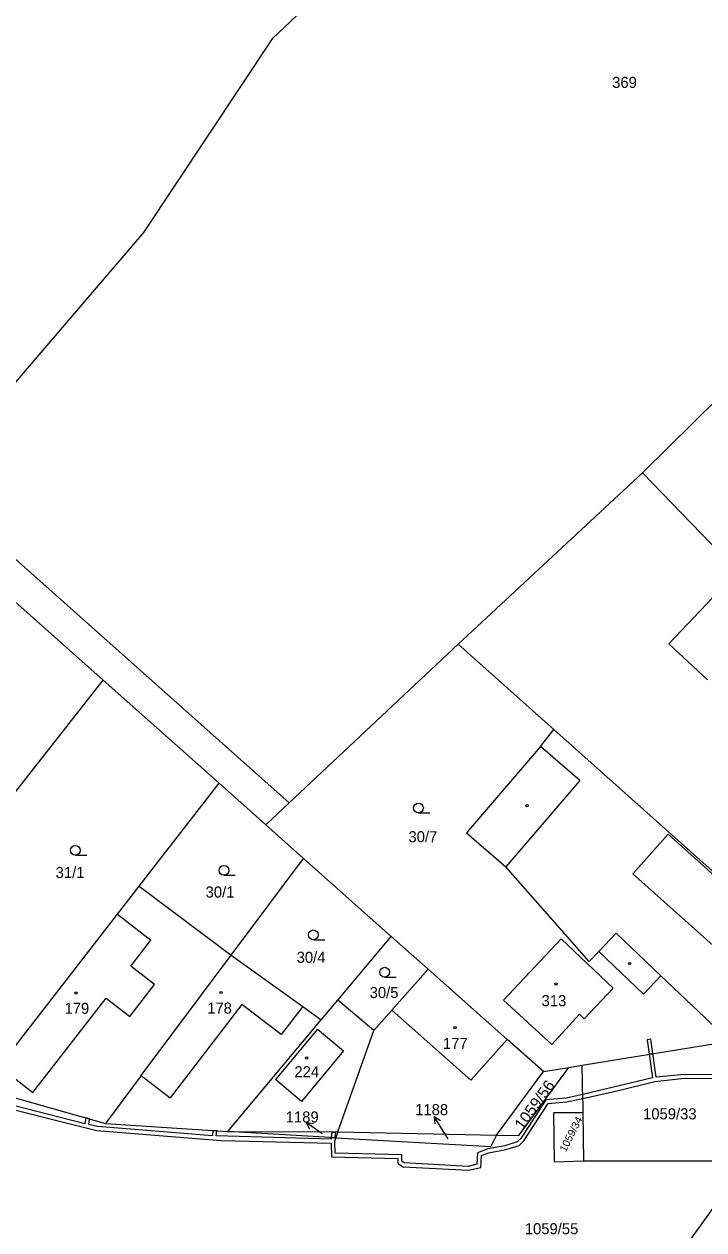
# Model space of a CAD drawing. Extents: x -694609 to -690140, y -1033292 to -1029794.
# Drawn here: x -692407.6 to -692303.2, y -1031470.7 to -1031285.6 of the extents above; entities that cross this region are included whole.
import ezdxf
from ezdxf.enums import TextEntityAlignment as Align

# ---------------------------------------------------------------- set-up
doc = ezdxf.new("R2010")
doc.units = 0
doc.header["$LTSCALE"] = 0.68
for name, color, linetype, lineweight in [('1', 7, 'Continuous', 25), ('13', 7, 'Continuous', 13), ('3', 7, 'Continuous', 25), ('4', 7, 'Continuous', 13), ('5', 7, 'Continuous', 25), ('7', 7, 'Continuous', 13)]:
    doc.layers.add(name, color=color, linetype=linetype, lineweight=lineweight)
doc.layers.add('2', color=7, linetype='Continuous')

msp = doc.modelspace()

# ---------------------------------------------------------------- linework, layer by layer
at = {"layer": '1'}
for p, q in [((-692351.12, -1031270.27), (-692369.47, -1031287.83)), ((-692369.47, -1031287.83), (-692389.22, -1031317.57)), ((-692389.22, -1031317.57), (-692422.13, -1031355.95)), ((-692300.88, -1031342.86), (-692312.61, -1031354.44)), ((-692340.93, -1031380.74), (-692312.61, -1031354.44)), ((-692297.6, -1031369.99), (-692312.61, -1031354.44)), ((-692366.85, -1031405.11), (-692422.13, -1031355.95)), ((-692395.42, -1031386.28), (-692410.37, -1031372.97)), ((-692308.57, -1031380.71), (-692299.9, -1031371.58)), ((-692366.85, -1031405.11), (-692340.93, -1031380.74)), ((-692340.93, -1031380.74), (-692326.24, -1031393.88)), ((-692302.61, -1031386.24), (-692308.57, -1031380.71)), ((-692420.58, -1031418.3), (-692395.42, -1031386.28)), ((-692377.64, -1031402.11), (-692395.42, -1031386.28)), ((-692328.3, -1031396.47), (-692326.24, -1031393.88)), ((-692282.48, -1031432.88), (-692326.24, -1031393.88)), ((-692328.3, -1031396.47), (-692339.66, -1031409.74)), ((-692389.89, -1031417.89), (-692377.64, -1031402.11)), ((-692370.46, -1031408.5), (-692377.64, -1031402.11)), ((-692370.46, -1031408.5), (-692366.85, -1031405.11)), ((-692364.66, -1031413.68), (-692370.46, -1031408.5)), ((-692339.66, -1031409.74), (-692333.58, -1031414.94)), ((-692375.76, -1031428.52), (-692364.66, -1031413.68)), ((-692351.21, -1031425.61), (-692364.66, -1031413.68)), ((-692320.78, -1031429.49), (-692333.58, -1031414.94)), ((-692393.22, -1031422.18), (-692389.89, -1031417.89)), ((-692389.89, -1031417.89), (-692375.76, -1031428.52)), ((-692411.4, -1031445.59), (-692393.22, -1031422.18)), ((-692345.54, -1031430.65), (-692351.21, -1031425.61)), ((-692325.13, -1031425.99), (-692333.94, -1031435.42)), ((-692317.12, -1031433.56), (-692325.13, -1031425.99)), ((-692389.58, -1031446.98), (-692375.76, -1031428.52)), ((-692375.76, -1031428.52), (-692364.79, -1031436.37)), ((-692319.32, -1031427.95), (-692320.78, -1031429.49)), ((-692312.45, -1031434.47), (-692319.32, -1031427.95)), ((-692345.54, -1031430.65), (-692351.11, -1031436.93)), ((-692333.38, -1031441.43), (-692345.54, -1031430.65)), ((-692309.78, -1031431.66), (-692312.45, -1031434.47)), ((-692299.22, -1031441.68), (-692309.78, -1031431.66)), ((-692317.12, -1031433.56), (-692321.56, -1031438.27)), ((-692353.88, -1031440.05), (-692359.42, -1031435.41)), ((-692326.55, -1031442.22), (-692333.94, -1031435.42)), ((-692364.79, -1031436.37), (-692361.94, -1031438.41)), ((-692351.11, -1031436.93), (-692353.88, -1031440.05)), ((-692322.3, -1031437.56), (-692326.55, -1031442.22)), ((-692321.56, -1031438.27), (-692322.3, -1031437.56)), ((-692376.31, -1031455.57), (-692361.94, -1031438.41)), ((-692359.39, -1031455.63), (-692353.88, -1031440.05)), ((-692327.81, -1031446.38), (-692333.38, -1031441.43)), ((-692321.9, -1031445.37), (-692299.22, -1031441.68)), ((-692323.94, -1031445.72), (-692321.9, -1031445.37)), ((-692321.78, -1031450.93), (-692321.9, -1031445.37)), ((-692389.58, -1031446.98), (-692395.05, -1031454.33)), ((-692335.02, -1031456.14), (-692327.81, -1031446.38)), ((-692331.58, -1031456.21), (-692323.94, -1031445.72)), ((-692327.81, -1031446.38), (-692323.94, -1031445.72)), ((-692414.04, -1031448.99), (-692395.05, -1031454.33)), ((-692326.22, -1031452.64), (-692321.76, -1031452.64)), ((-692326.13, -1031460.27), (-692326.22, -1031452.64)), ((-692321.78, -1031450.93), (-692321.76, -1031452.64)), ((-692321.76, -1031452.64), (-692321.65, -1031460.14)), ((-692395.05, -1031454.33), (-692376.31, -1031455.57)), ((-692359.7, -1031456.52), (-692376.31, -1031455.57)), ((-692376.31, -1031455.57), (-692359.39, -1031455.63)), ((-692359.39, -1031455.63), (-692359.7, -1031456.52)), ((-692359.39, -1031455.63), (-692335.02, -1031456.14)), ((-692335.02, -1031456.14), (-692335.92, -1031457.88)), ((-692335.02, -1031456.14), (-692331.58, -1031456.21)), ((-692359.7, -1031456.52), (-692335.92, -1031457.88)), ((-692321.65, -1031460.14), (-692326.13, -1031460.27)), ((-692296.63, -1031460.11), (-692321.65, -1031460.14)), ((-692296.63, -1031460.11), (-692310.42, -1031479.32))]:
    msp.add_line(p, q, dxfattribs=at)
msp.add_lwpolyline([(-692361.94, -1031438.41), (-692359.42, -1031435.41), (-692351.21, -1031425.61)], dxfattribs=at)
at = {"layer": '13'}
for points in [[(-692311.92, -1031441.51), (-692311.61, -1031443.7), (-692311.02, -1031443.6), (-692311.33, -1031441.39)], [(-692360.33, -1031455.72), (-692360.4, -1031456.48), (-692359.8, -1031456.51), (-692359.73, -1031455.73)]]:
    msp.add_lwpolyline(points, close=True, dxfattribs=at)
for points in [[(-692292.95, -1031446.89), (-692306.17, -1031446.8), (-692310.5, -1031447.24), (-692311.02, -1031443.6), (-692311.61, -1031443.7), (-692311.09, -1031447.35), (-692321.8, -1031449.88), (-692324.35, -1031450.44), (-692327.46, -1031450.69), (-692331.3, -1031456.62), (-692331.88, -1031457.18), (-692333.73, -1031457.77), (-692336.39, -1031458.25), (-692337.93, -1031458.83), (-692338.03, -1031460.6), (-692339.41, -1031460.92), (-692349.19, -1031460.39), (-692349.59, -1031460.14), (-692349.56, -1031459.13), (-692359.81, -1031458.88), (-692359.85, -1031457.08), (-692359.7, -1031456.52), (-692360.4, -1031456.48), (-692360.42, -1031456.76), (-692378.06, -1031456.26), (-692377.99, -1031455.46), (-692378.59, -1031455.42)], [(-692414.65, -1031450.86), (-692396.4, -1031455.42), (-692377.33, -1031456.93), (-692360.44, -1031457.36), (-692360.39, -1031459.46), (-692350.18, -1031459.71), (-692350.21, -1031460.46), (-692349.37, -1031460.99), (-692339.35, -1031461.52), (-692337.45, -1031461.08), (-692337.35, -1031459.25), (-692336.23, -1031458.83), (-692333.59, -1031458.35), (-692331.56, -1031457.7), (-692330.84, -1031457), (-692327.12, -1031451.27), (-692324.27, -1031451.04), (-692321.79, -1031450.49), (-692316.31, -1031449.28), (-692310.71, -1031447.87), (-692306.15, -1031447.4), (-692292.65, -1031447.49)], [(-692378.59, -1031455.42), (-692378.66, -1031456.24), (-692396.3, -1031454.82), (-692397.64, -1031454.51), (-692397.52, -1031453.63), (-692398.11, -1031453.47), (-692398.23, -1031454.37), (-692413.03, -1031450.59)]]:
    msp.add_lwpolyline(points, dxfattribs=at)
at = {"layer": '3'}
for p, q in [((-692347.013, -1031406.65), (-692345.263, -1031406.65)), ((-692399.693, -1031413.16), (-692397.943, -1031413.16)), ((-692376.893, -1031416.23), (-692375.143, -1031416.23)), ((-692363.153, -1031426.13), (-692361.403, -1031426.13)), ((-692352.213, -1031431.86), (-692350.463, -1031431.86))]:
    msp.add_line(p, q, dxfattribs=at)
for centre in [(-692347.0129, -1031405.8998), (-692399.6929, -1031412.4098), (-692376.8929, -1031415.4798), (-692363.1529, -1031425.3798), (-692352.2129, -1031431.1098)]:
    msp.add_circle(centre, 0.75, dxfattribs=at)
at = {"layer": '4'}
for p, q in [((-692322.22, -1031401.67), (-692328.3, -1031396.47)), ((-692322.22, -1031401.67), (-692333.58, -1031414.94)), ((-692308.68, -1031409.94), (-692314.1, -1031416)), ((-692286.89, -1031429.49), (-692308.68, -1031409.94)), ((-692301.77, -1031427.03), (-692314.1, -1031416)), ((-692393.22, -1031422.18), (-692388.09, -1031426.19)), ((-692391.2, -1031430.2), (-692388.09, -1031426.19)), ((-692316.65, -1031425.13), (-692319.32, -1031427.95)), ((-692309.78, -1031431.66), (-692316.65, -1031425.13)), ((-692387.57, -1031433.02), (-692391.2, -1031430.2)), ((-692391.36, -1031437.9), (-692387.57, -1031433.02)), ((-692406.25, -1031449.58), (-692394.99, -1031435.08)), ((-692394.99, -1031435.08), (-692391.36, -1031437.9)), ((-692364.79, -1031436.37), (-692368.11, -1031440.69)), ((-692362.5, -1031439.86), (-692368.99, -1031447.61)), ((-692362.5, -1031439.86), (-692358.51, -1031443.2)), ((-692411.4, -1031445.59), (-692406.25, -1031449.58)), ((-692389.58, -1031446.98), (-692385.13, -1031450.4))]:
    msp.add_line(p, q, dxfattribs=at)
for points in [[(-692368.11, -1031440.69), (-692374.12, -1031436.07), (-692385.13, -1031450.4)], [(-692351.11, -1031436.93), (-692338.96, -1031447.71), (-692333.38, -1031441.43)], [(-692358.51, -1031443.2), (-692365, -1031450.95), (-692368.99, -1031447.61)]]:
    msp.add_lwpolyline(points, dxfattribs=at)
at = {"layer": '5'}
for centre in [(-692330.3468, -1031405.5492), (-692314.5968, -1031429.7792), (-692399.5968, -1031434.3092), (-692377.3268, -1031434.2292), (-692325.8868, -1031432.9092), (-692341.4268, -1031439.6492), (-692364.1768, -1031444.2892)]:
    msp.add_circle(centre, 0.175, dxfattribs=at)
at = {"layer": '7'}
for p, q in [((-692364.248, -1031454.176), (-692363.732, -1031455.17)), ((-692344.6, -1031453.285), (-692344.494, -1031454.4))]:
    msp.add_line(p, q, dxfattribs=at)
for points in [[(-692361.82, -1031455.94), (-692364.248, -1031454.176), (-692363.143, -1031454.36)], [(-692342.45, -1031456.72), (-692343.01, -1031455.83), (-692344.6, -1031453.285), (-692343.645, -1031453.869)]]:
    msp.add_lwpolyline(points, dxfattribs=at)

# ---------------------------------------------------------------- texts
at = {"layer": '2'}
for s, p in [('369', (-692315.379, -1031295.355)), ('30/7', (-692346.339, -1031411.165)), ('31/1', (-692400.519, -1031416.655)), ('30/1', (-692377.489, -1031419.655)), ('30/4', (-692363.509, -1031429.675)), ('30/5', (-692352.299, -1031435.085)), ('179', (-692399.469, -1031437.505)), ('178', (-692377.559, -1031437.475)), ('313', (-692326.219, -1031436.335)), ('177', (-692341.359, -1031442.895)), ('224', (-692364.169, -1031447.245)), ('1189', (-692364.87, -1031454.185)), ('1188', (-692344.99, -1031453.065)), ('1059/33', (-692308.419, -1031453.705)), ('1059/55', (-692326.579, -1031471.345))]:
    msp.add_text(s, height=1.7, dxfattribs=at).set_placement(p, align=Align.CENTER)
at = {"layer": '2', "width": 1.05}
for s, height, rotation, p in [('1059/56', 1.7, 54, (-692328.5114, -1031451.9656)), ('1059/34', 1.139, 63, (-692323.0987, -1031456.2365))]:
    msp.add_text(s, height=height, rotation=rotation, dxfattribs=at).set_placement(p, align=Align.CENTER)

doc.saveas('drawing.dxf')
